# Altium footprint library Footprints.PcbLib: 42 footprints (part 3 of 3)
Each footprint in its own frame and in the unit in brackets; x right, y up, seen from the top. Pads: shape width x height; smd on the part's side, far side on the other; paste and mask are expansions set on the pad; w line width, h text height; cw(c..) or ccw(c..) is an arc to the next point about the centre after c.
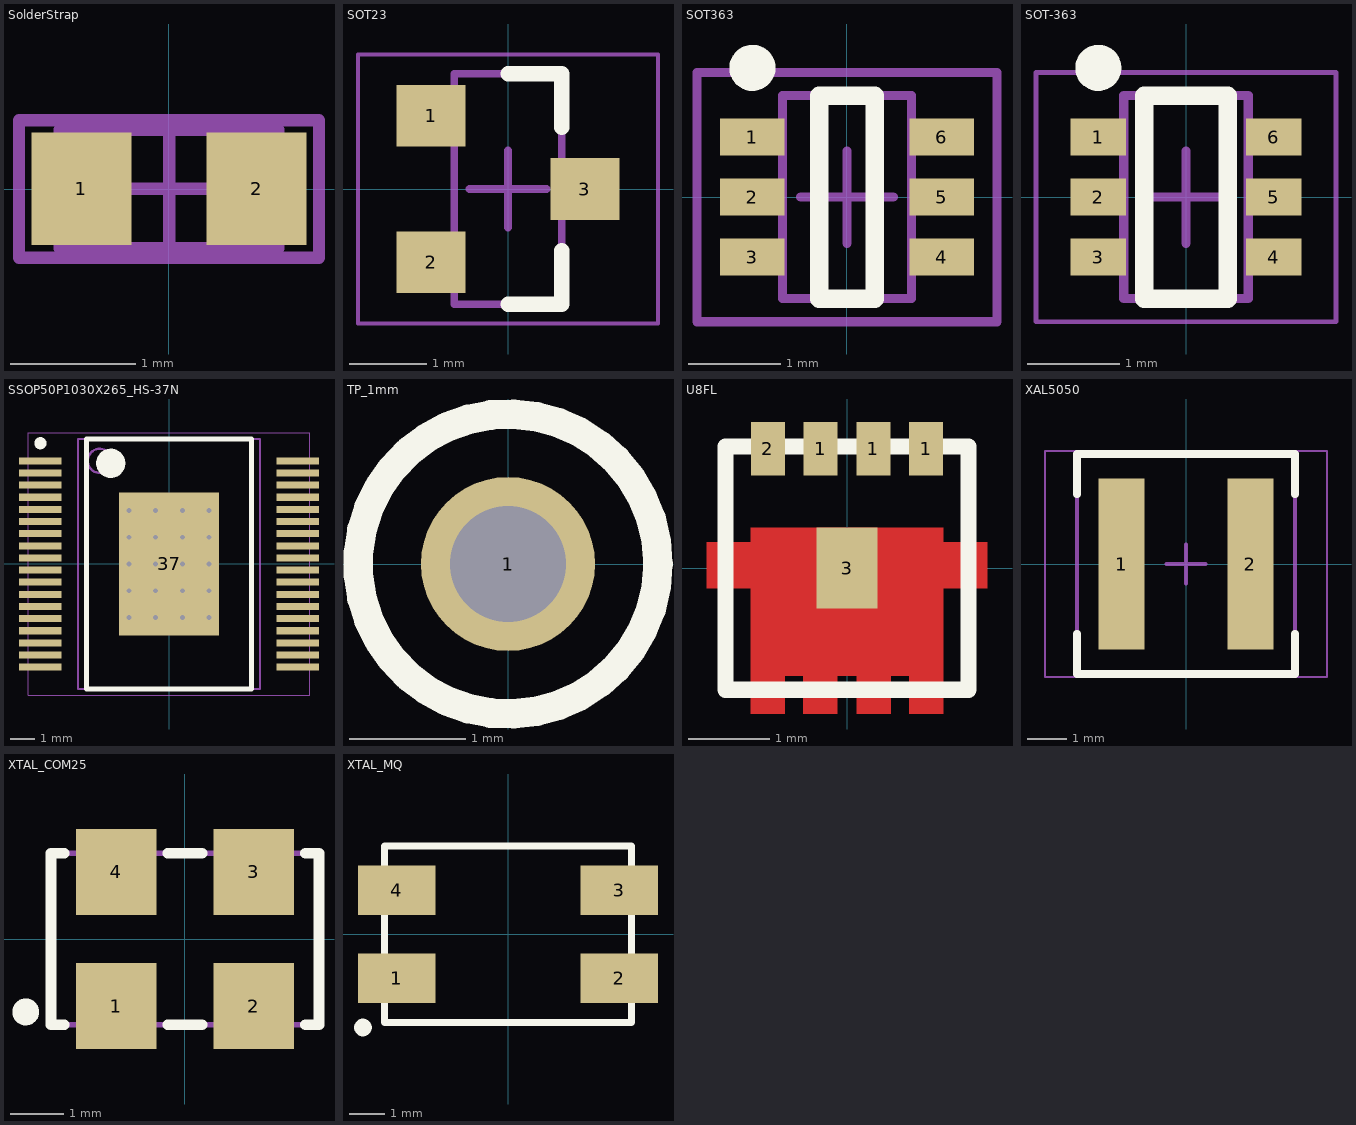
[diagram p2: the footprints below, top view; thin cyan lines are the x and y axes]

## SolderStrap [mm] "Solder Strap"
height 1.3
pads (2):
  rect 0.8x0.9 smd: 1(-0.7,0) 2(0.7,0)
Top Solder:
  rectangle: -0.325,-0.55 0.475,0.55
Mechanical 13:
  lines w0.1: -0.875,-0.475 0.875,-0.475 0.875,0.475 -0.875,0.475 -0.875,-0.475
Mechanical 15:
  lines w0.1: -0.475,0 0.475,0 ; 0,-0.475 0,0.475 ; -1.2,-0.55 1.2,-0.55 1.2,0.55 -1.2,0.55 -1.2,-0.55
3D body: height 0.5, standoff 0, extent -0.875,-0.475 0.875,0.475

## SOT23 [mm] "SOT23, 3-Leads, Body 2.90x2.37mm, Pitch 0.95mm, IPC Medium Density"
height 1.1
pads (3):
  rect 0.9x0.8 smd: 1(-1,0.95) 2(-1,-0.95) 3(1,0)
Top Overlay:
  lines w0.2: 0,-1.5 0.7,-1.5 0.7,-0.8 ; 0,1.5 0.7,1.5 0.7,0.8
Mechanical 13:
  lines w0.1: -0.7,-1.5 -0.7,1.5 0.7,1.5 0.7,-1.5 -0.7,-1.5
Mechanical 15:
  lines w0.05: -1.95,-1.75 -1.95,1.75 1.95,1.75 1.95,-1.75 -1.95,-1.75
  lines w0.1: -0.5,0 0.5,0 ; 0,-0.5 0,0.5
3D body: height 0.94, standoff -0.04, extent -1.299,-1.45 1.249,1.47

## SOT363 [mm] "SOT363, 6-Leads, Body 2x1.3mm, Pitch 0.65mm, Lead Span 2.1mm, IPC Medium Density"
height 1.1
pads (6):
  rect 0.7x0.4 smd mask+0: 1(-1.025,0.65) 2(-1.025,0) 3(-1.025,-0.65) 4(1.025,-0.65) 5(1.025,0) 6(1.025,0.65)
Top Overlay:
  circle w0.25: c-1.025,1.4 r0.125
  lines w0.2: -0.3,-1.1 0.3,-1.1 0.3,1.1 -0.3,1.1 -0.3,-1.1
Top Solder:
  rectangle: -1.475,-0.95 -0.575,0.95
  rectangle: 0.575,-0.95 1.475,0.95
Mechanical 13:
  lines w0.1: -0.7,-1.1 -0.7,1.1 0.7,1.1 0.7,-1.1 -0.7,-1.1
Mechanical 15:
  lines w0.1: -0.5,0 0.5,0 ; 0,-0.5 0,0.5 ; -1.625,-1.35 -1.625,1.35 1.625,1.35 1.625,-1.35 -1.625,-1.35
3D body: height 1, standoff 0, extent -1.15,-1.05 1.15,1.05

## SOT-363 [mm]
height 1.1
pads (6):
  rect 0.6x0.4 smd mask+0: 1(-0.95,0.65) 2(-0.95,0) 3(-0.95,-0.65) 4(0.95,-0.65) 5(0.95,0) 6(0.95,0.65)
Top Overlay:
  circle w0.25: c-0.95,1.4 r0.125
  lines w0.2: -0.45,-1.1 0.45,-1.1 0.45,1.1 -0.45,1.1 -0.45,-1.1
Top Solder:
  rectangle: 0.55,-0.95 1.35,0.95
  rectangle: -1.35,-0.95 -0.55,0.95
Mechanical 13:
  lines w0.1: -0.675,-1.1 -0.675,1.1 0.675,1.1 0.675,-1.1 -0.675,-1.1
Mechanical 15:
  lines w0.05: -1.625,-1.35 -1.625,1.35 1.625,1.35 1.625,-1.35 -1.625,-1.35
  lines w0.1: -0.5,0 0.5,0 ; 0,-0.5 0,0.5
3D body: height 1, standoff 0, extent -1.15,-1.05 1.15,1.05

## SSOP50P1030X265_HS-37N [mm] "SSOP, 36-Leads, Body 10.30x7.50mm, Pitch 0.50mm, Thermal Pad 5.90.2x4.10.2mm, IPC Medium Density"
height 2.65
pads (37):
  rect 1.76x0.29 smd: 1(-5.3,4.25) 2(-5.3,3.75) 3(-5.3,3.25) 4(-5.3,2.75) 5(-5.3,2.25) 6(-5.3,1.75) 7(-5.3,1.25) 8(-5.3,0.75) 9(-5.3,0.25) 10(-5.3,-0.25) 11(-5.3,-0.75) 12(-5.3,-1.25) 13(-5.3,-1.75) 14(-5.3,-2.25) 15(-5.3,-2.75) 16(-5.3,-3.25) 17(-5.3,-3.75) 18(-5.3,-4.25) 19(5.3,-4.25) 20(5.3,-3.75) 21(5.3,-3.25) 22(5.3,-2.75) 23(5.3,-2.25) 24(5.3,-1.75) 25(5.3,-1.25) 26(5.3,-0.75) 27(5.3,-0.25) 28(5.3,0.25) 29(5.3,0.75) 30(5.3,1.25) 31(5.3,1.75) 32(5.3,2.25) 33(5.3,2.75) 34(5.3,3.25) 35(5.3,3.75) 36(5.3,4.25)
  rect 4.1x5.9 smd: 37(0,0)
via -1.65,2.2 diameter 0.5 hole 0.2
via -0.55,2.2 diameter 0.5 hole 0.2
via 0.55,2.2 diameter 0.5 hole 0.2
via 1.65,2.2 diameter 0.5 hole 0.2
via -1.65,1.1 diameter 0.5 hole 0.2
via -0.55,1.1 diameter 0.5 hole 0.2
via 0.55,1.1 diameter 0.5 hole 0.2
via 1.65,1.1 diameter 0.5 hole 0.2
via -1.65,0 diameter 0.5 hole 0.2
via -0.55,0 diameter 0.5 hole 0.2
via 0.55,0 diameter 0.5 hole 0.2
via 1.65,0 diameter 0.5 hole 0.2
via -1.65,-1.1 diameter 0.5 hole 0.2
via -0.55,-1.1 diameter 0.5 hole 0.2
via 0.55,-1.1 diameter 0.5 hole 0.2
via 1.65,-1.1 diameter 0.5 hole 0.2
via -1.65,-2.2 diameter 0.5 hole 0.2
via -0.55,-2.2 diameter 0.5 hole 0.2
via 0.55,-2.2 diameter 0.5 hole 0.2
via 1.65,-2.2 diameter 0.5 hole 0.2
Top Overlay:
  circle w0.25: c-5.3,4.975 r0.125
  circle w0.6: c-2.4,4.15 r0.3
  lines w0.2: -3.4,-5.15 -3.4,5.15 3.4,5.15 3.4,-5.15 -3.4,-5.15
Mechanical 13:
  circle w0.1: c-2.85,4.25 r0.5
  lines w0.1: -3.75,-5.15 -3.75,5.15 3.75,5.15 3.75,-5.15 -3.75,-5.15
Mechanical 15:
  lines w0.05: -5.8,-5.4 -5.8,5.4 5.8,5.4 5.8,-5.4 -5.8,-5.4
  lines w0.1: -0.5,0 0.5,0 ; 0,-0.5 0,0.5
3D body: height 2.65, standoff 0.1, extent -3.75,-5.15 3.75,5.15

## TP_1mm [mm] "Testpoint DIA 1mm"
height 5
pads (1):
  round 1.5 hole 1: 1(0,0)
Top Overlay:
  circle w0.254: c0,0 r1.291
3D body: height 4.89, standoff -3.07, extent -1.27,-1.27 1.27,1.27

## U8FL [mm]
height 0.75
pads (5):
  rect 0.42x0.66 smd mask+0: 1(-0.325,1.47) 1(0.325,1.47) 1(0.975,1.47) 2(-0.975,1.47)
  rect 0.75x1 smd: 3(0,0)
Top Layer:
  region: -1.19,0.5 -1.19,0.32 -1.73,0.32 -1.73,-0.25 -1.19,-0.25 -1.19,-1.8 -0.77,-1.8 -0.77,-1.33 -0.54,-1.33 -0.54,-1.8 -0.12,-1.8 -0.12,-1.33 0.12,-1.33 0.12,-1.8 0.54,-1.8 0.54,-1.33 0.77,-1.33 0.77,-1.8 1.19,-1.8 1.19,-0.25 1.73,-0.25 1.73,0.32 1.19,0.32 1.19,0.5
Top Overlay:
  lines w0.2: -1.5,-1.5 1.5,-1.5 1.5,1.5 -1.5,1.5 -1.5,-1.5
Top Solder:
  rectangle: -1.3,1.05 1.3,1.9
3D body: height 0.8, standoff 0, extent -1.5,-1.52 1.5,1.5

## XAL5050 [mm] "Precision Wire Wound Inductor, 2-Leads, Coilcraft XAL5050"
height 5.1
pads (2):
  rect 1.18x4.4 smd: 1(-1.655,0) 2(1.655,0)
Top Overlay:
  lines w0.2: -2.8,-1.795 -2.8,-2.825 2.8,-2.825 2.8,-1.795 ; -2.8,1.795 -2.8,2.825 2.8,2.825 2.8,1.795
Mechanical 13:
  lines w0.1: -2.8,-2.85 2.8,-2.85 2.8,2.825 -2.8,2.825 -2.8,-2.85
Mechanical 15:
  lines w0.05: -3.625,-2.9 3.625,-2.9 3.625,2.9 -3.625,2.9 -3.625,-2.9
  lines w0.1: -0.5,0 0.5,0 ; 0,-0.5 0,0.5
3D body: height 5, standoff -0.1, extent -2.74,-2.84 2.74,2.84

## XTAL_COM25 [mm]
height 1
pads (4):
  rect 1.5x1.6 smd: 1(-1.28,-1.25) 2(1.28,-1.25) 3(1.28,1.25) 4(-1.28,1.25)
Top Overlay:
  circle w0.25: c-2.97,-1.36 r0.125
  lines w0.2: -2.25,-1.6 -2.5,-1.6 -2.5,1.6 -2.25,1.6 ; -0.32,-1.6 0.32,-1.6 ; -0.32,1.6 0.32,1.6 ; 2.25,-1.6 2.5,-1.6 2.5,1.6 2.25,1.6
Mechanical 13:
  lines w0.1: -2.51,-1.6 2.5,-1.6 2.5,1.6 -2.51,1.6 -2.51,-1.6
3D body: height 1, standoff 0.05, extent -2.51,-1.6 2.5,1.6

## XTAL_MQ [mm]
height 1.2
pads (4):
  rect 2.2x1.4 smd mask+0.102: 1(-3.15,-1.25)
  rect 2.2x1.4 smd: 2(3.15,-1.25) 3(3.15,1.25) 4(-3.15,1.25)
Top Overlay:
  circle w0.25: c-4.11,-2.64 r0.125
  lines w0.2: -3.5,-2.5 3.5,-2.5 3.5,2.5 -3.5,2.5 -3.5,-2.5
Mechanical 13:
  lines w0.1: -3.5,-2.5 -3.5,2.5 3.5,2.5 3.5,-2.5 -3.5,-2.5
3D body: height 1.2, standoff 0.05, extent -3.5,-2.5 3.5,2.5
